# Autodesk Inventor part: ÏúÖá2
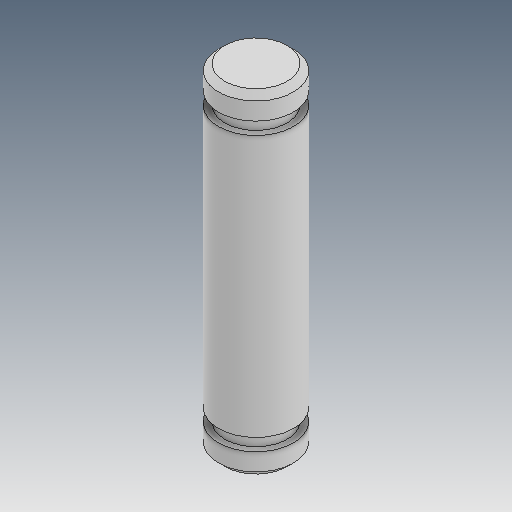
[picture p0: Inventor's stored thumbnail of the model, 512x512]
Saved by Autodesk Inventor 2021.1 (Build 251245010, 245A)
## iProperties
Created: 2015-08
Part Number: ÏúÖá2
Material: Ogólny
Document SubType Name: Modeling
Designer: user
Density: 1 g/cm^3
Appearance: Domyślna
Author: user
Revision Number: ÈÎºÎ
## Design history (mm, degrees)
feature "Ðý×ª1"
node "Bryła1"
